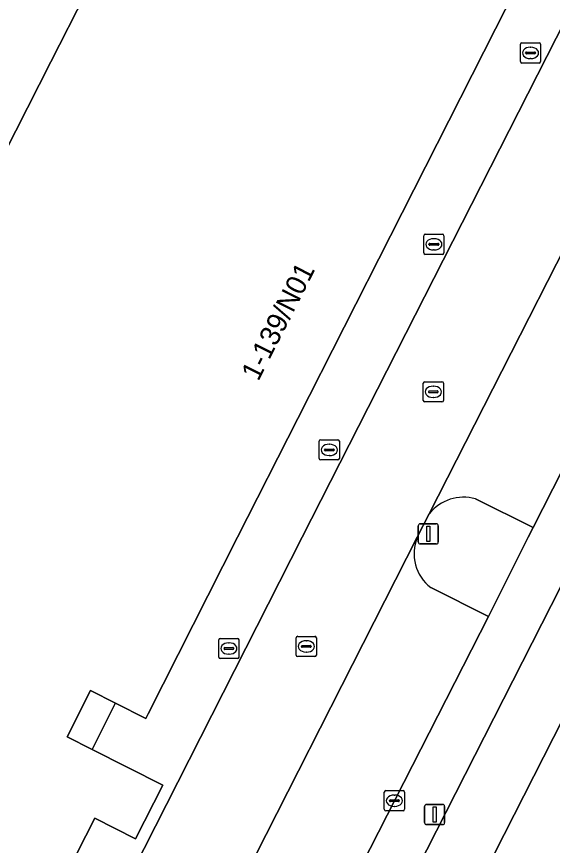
# Model space of a CAD drawing. Extents: x 161241 to 161758, y 384138 to 384885.
# Drawn here: x 161558.34 to 161584.85, y 384484.75 to 384525.77 of the extents above; entities that cross this region are included whole.
import ezdxf

# ---------------------------------------------------------------- set-up
doc = ezdxf.new("R2010")
doc.units = 0
for name, color, linetype in [('IMGEO_Berm_groen', 7, 'Continuous'), ('IMGEO_Erf', 7, 'Continuous'), ('IMGEO_Fietspad_gesloten', 7, 'Continuous'), ('IMGEO_Groenvoorziening', 7, 'Continuous'), ('IMGEO_Haag', 7, 'Continuous'), ('IMGEO_Kolk', 7, 'Continuous'), ('IMGEO_Lichtmast', 7, 'Continuous'), ('IMGEO_Pand', 7, 'Continuous'), ('IMGEO_Pand_nummerreeks', 7, 'Continuous'), ('IMGEO_Pand_overbouw', 7, 'Continuous'), ('IMGEO_Parkeervlak_open', 7, 'Continuous'), ('IMGEO_Rijbaan_lokaal_open', 7, 'Continuous'), ('IMGEO_Rioolput', 7, 'Continuous'), ('IMGEO_Voetpad_open', 7, 'Continuous')]:
    doc.layers.add(name, color=color, linetype=linetype)

msp = doc.modelspace()

# ---------------------------------------------------------------- linework, layer by layer
at = {"layer": 'IMGEO_Berm_groen'}
msp.add_lwpolyline([(161628.393, 384575.761), (161628.195, 384575.423), (161627.927, 384574.874), (161627.772, 384574.506), (161627.114, 384573.143), (161550.415, 384422.299), (161526.535, 384375.146), (161520.707, 384363.649)], dxfattribs=at)
at = {"layer": 'IMGEO_Erf'}
msp.add_lwpolyline([(161545.574, 384495.041), (161546.917, 384494.362), (161549.173, 384498.829), (161547.837, 384499.52), (161548.081, 384500), (161550.264, 384504.297), (161555.424, 384514.452), (161560.039, 384523.536), (161565.227, 384533.748), (161567.615, 384538.447), (161568.979, 384537.766), (161570.138, 384540.132), (161570.443, 384542.795), (161568.946, 384542.971), (161569.566, 384548.298), (161570.885, 384559.629), (161572.061, 384569.733), (161573.384, 384581.093), (161574.574, 384591.319), (161575.896, 384602.674)], dxfattribs=at)
at = {"layer": 'IMGEO_Fietspad_gesloten'}
for points in [[(161627.927, 384574.874), (161628.195, 384575.423), (161625.518, 384576.727), (161548.308, 384424.931), (161522.72, 384374.49), (161518.014, 384365.014)], [(161520.707, 384363.649), (161526.535, 384375.146), (161550.415, 384422.299), (161627.114, 384573.143), (161627.772, 384574.506), (161627.927, 384574.874)]]:
    msp.add_lwpolyline(points, dxfattribs=at)
at = {"layer": 'IMGEO_Groenvoorziening'}
for points in [[(161583.652, 384500), (161583.893, 384500.478), (161581.038, 384501.902)], [(161578.756, 384501.165), (161578.163, 384500)], [(161578.826, 384497.506), (161581.681, 384496.083), (161583.652, 384500)]]:
    msp.add_lwpolyline(points, dxfattribs=at)
for centre, radius, start, end in [((161580.452, 384499.816), 2.167, 74.3044, 141.4926), ((161580.118, 384499.185), 2.118, 157.362, 232.4122)]:
    msp.add_arc(centre, radius, start, end, dxfattribs=at)
at = {"layer": 'IMGEO_Haag'}
for points in [[(161578.826, 384497.506), (161581.681, 384496.083), (161583.652, 384500), (161583.893, 384500.478), (161581.038, 384501.902)], [(161578.756, 384501.165), (161578.163, 384500)]]:
    msp.add_lwpolyline(points, dxfattribs=at)
for centre, radius, start, end in [((161580.452, 384499.816), 2.167, 74.3044, 141.4926), ((161580.118, 384499.185), 2.118, 157.362, 232.4122)]:
    msp.add_arc(centre, radius, start, end, dxfattribs=at)
at = {"layer": 'IMGEO_Kolk'}
for p, q in [((161578.456, 384506.773), (161578.456, 384507.625)), ((161578.531, 384507.699), (161579.383, 384507.699)), ((161579.457, 384507.625), (161579.457, 384506.773)), ((161578.715, 384507.193), (161578.715, 384507.205)), ((161579.153, 384507.156), (161578.755, 384507.156)), ((161578.758, 384507.242), (161579.156, 384507.242)), ((161578.944, 384507.479), (161578.969, 384507.479)), ((161579.199, 384507.205), (161579.199, 384507.193)), ((161579.383, 384506.699), (161578.531, 384506.699)), ((161578.967, 384506.919), (161578.942, 384506.919)), ((161572.172, 384494.17), (161572.172, 384495.022)), ((161572.247, 384495.096), (161573.099, 384495.096)), ((161572.66, 384494.876), (161572.685, 384494.876)), ((161573.173, 384495.022), (161573.173, 384494.17)), ((161572.431, 384494.59), (161572.431, 384494.602)), ((161572.869, 384494.553), (161572.471, 384494.553)), ((161572.474, 384494.639), (161572.872, 384494.639)), ((161572.915, 384494.602), (161572.915, 384494.59)), ((161573.099, 384494.096), (161572.247, 384494.096)), ((161572.683, 384494.316), (161572.658, 384494.316)), ((161576.606, 384487.46), (161577.458, 384487.46)), ((161576.531, 384486.534), (161576.531, 384487.386)), ((161576.833, 384487.003), (161577.231, 384487.003)), ((161577.019, 384487.24), (161577.044, 384487.24)), ((161577.532, 384487.386), (161577.532, 384486.534)), ((161576.79, 384486.954), (161576.79, 384486.966)), ((161577.228, 384486.917), (161576.83, 384486.917)), ((161577.042, 384486.68), (161577.017, 384486.68)), ((161577.274, 384486.966), (161577.274, 384486.954)), ((161577.458, 384486.46), (161576.606, 384486.46))]:
    msp.add_line(p, q, dxfattribs=at)
for points in [[(161578.456, 384506.773), (161578.456, 384507.625)], [(161578.531, 384507.699), (161579.383, 384507.699)], [(161579.457, 384507.625), (161579.457, 384506.773)], [(161579.383, 384506.699), (161578.531, 384506.699)], [(161572.172, 384494.17), (161572.172, 384495.022)], [(161572.247, 384495.096), (161573.099, 384495.096)], [(161573.173, 384495.022), (161573.173, 384494.17)], [(161573.099, 384494.096), (161572.247, 384494.096)], [(161576.606, 384487.46), (161577.458, 384487.46)], [(161576.531, 384486.534), (161576.531, 384487.386)], [(161577.532, 384487.386), (161577.532, 384486.534)], [(161577.458, 384486.46), (161576.606, 384486.46)]]:
    msp.add_lwpolyline(points, dxfattribs=at)
for centre, radius, start, end in [((161578.533, 384507.623), 0.0765, 91.552, 178.448), ((161578.533, 384507.623), 0.0765, 91.552, 178.448), ((161579.381, 384507.623), 0.0765, 1.552, 88.448), ((161579.381, 384507.623), 0.0765, 1.552, 88.448), ((161578.755, 384507.202), 0.0403, 85.8775, 175.7526), ((161578.752, 384507.192), 0.0366, 178.938, 274.7102), ((161579.156, 384507.199), 0.043, 264.8664, 352.4533), ((161579.16, 384507.204), 0.0386, 1.7309, 96.639), ((161578.533, 384506.775), 0.0765, 181.552, 268.448), ((161578.533, 384506.775), 0.0765, 181.552, 268.448), ((161579.381, 384506.775), 0.0765, 271.552, 358.448), ((161579.381, 384506.775), 0.0765, 271.552, 358.448), ((161572.249, 384495.02), 0.0765, 91.552, 178.448), ((161572.249, 384495.02), 0.0765, 91.552, 178.448), ((161573.097, 384495.02), 0.0765, 1.552, 88.448), ((161573.097, 384495.02), 0.0765, 1.552, 88.448), ((161572.471, 384494.599), 0.0403, 85.8775, 175.7526), ((161572.468, 384494.589), 0.0366, 178.938, 274.7102), ((161572.872, 384494.596), 0.043, 264.8664, 352.4533), ((161572.876, 384494.601), 0.0386, 1.7309, 96.639), ((161572.249, 384494.172), 0.0765, 181.552, 268.448), ((161572.249, 384494.172), 0.0765, 181.552, 268.448), ((161573.097, 384494.172), 0.0765, 271.552, 358.448), ((161573.097, 384494.172), 0.0765, 271.552, 358.448), ((161576.608, 384487.384), 0.0765, 91.552, 178.448), ((161576.608, 384487.384), 0.0765, 91.552, 178.448), ((161577.456, 384487.384), 0.0765, 1.552, 88.448), ((161577.456, 384487.384), 0.0765, 1.552, 88.448), ((161576.83, 384486.963), 0.0403, 85.8775, 175.7526), ((161577.235, 384486.965), 0.0386, 1.7309, 96.639), ((161576.827, 384486.953), 0.0366, 178.938, 274.7102), ((161577.231, 384486.96), 0.043, 264.8664, 352.4533), ((161576.608, 384486.536), 0.0765, 181.552, 268.448), ((161576.608, 384486.536), 0.0765, 181.552, 268.448), ((161577.456, 384486.536), 0.0765, 271.552, 358.448), ((161577.456, 384486.536), 0.0765, 271.552, 358.448)]:
    msp.add_arc(centre, radius, start, end, dxfattribs=at)
for centre, major_axis, ratio, start_param, end_param in [((161578.943, 384507.199), (-0.387, 0.002), 0.722429, 4.712389, 7.853982), ((161578.968, 384507.199), (-0.39, 0.002), 0.717154, 1.570796, 4.712389), ((161572.659, 384494.596), (-0.387, 0.002), 0.722429, 4.712389, 7.853982), ((161572.684, 384494.596), (-0.39, 0.002), 0.717154, 1.570796, 4.712389), ((161577.018, 384486.96), (-0.387, 0.002), 0.722429, 4.712389, 7.853982), ((161577.043, 384486.96), (-0.39, 0.002), 0.717154, 1.570796, 4.712389)]:
    msp.add_ellipse(centre, major_axis=major_axis, ratio=ratio, start_param=start_param, end_param=end_param, dxfattribs=at)
at = {"layer": 'IMGEO_Lichtmast'}
for p, q in [((161578.211, 384499.768), (161578.211, 384500.568)), ((161578.211, 384500.568), (161578.211, 384499.768)), ((161578.311, 384500.668), (161579.101, 384500.668)), ((161579.101, 384500.668), (161578.311, 384500.668)), ((161579.201, 384500.568), (161579.201, 384499.768)), ((161579.201, 384499.768), (161579.201, 384500.568)), ((161579.101, 384499.668), (161578.311, 384499.668)), ((161578.311, 384499.668), (161579.101, 384499.668)), ((161578.523, 384485.876), (161578.523, 384486.676)), ((161578.523, 384486.676), (161578.523, 384485.876)), ((161578.623, 384486.776), (161579.413, 384486.776)), ((161579.413, 384486.776), (161578.623, 384486.776)), ((161579.513, 384486.676), (161579.513, 384485.876)), ((161579.513, 384485.876), (161579.513, 384486.676)), ((161579.413, 384485.776), (161578.623, 384485.776)), ((161578.623, 384485.776), (161579.413, 384485.776))]:
    msp.add_line(p, q, dxfattribs=at)
for points in [[(161578.631, 384500.543), (161578.781, 384500.543), (161578.781, 384499.793), (161578.631, 384499.793), (161578.631, 384500.543)], [(161578.943, 384486.651), (161579.093, 384486.651), (161579.093, 384485.901), (161578.943, 384485.901), (161578.943, 384486.651)]]:
    msp.add_lwpolyline(points, dxfattribs=at)
for centre, start, end in [((161578.311, 384500.568), 90, 180), ((161578.311, 384500.568), 90, 180), ((161579.101, 384500.568), 0, 90), ((161579.101, 384500.568), 360, 90), ((161578.311, 384499.768), 180, 270), ((161578.311, 384499.768), 180, 270), ((161579.101, 384499.768), 270, 0), ((161579.101, 384499.768), 270, 0), ((161578.623, 384486.676), 90, 180), ((161578.623, 384486.676), 90, 180), ((161579.413, 384486.676), 0, 90), ((161579.413, 384486.676), 360, 90), ((161578.623, 384485.876), 180, 270), ((161578.623, 384485.876), 180, 270), ((161579.413, 384485.876), 270, 0), ((161579.413, 384485.876), 270, 0)]:
    msp.add_arc(centre, 0.1, start, end, dxfattribs=at)
at = {"layer": 'IMGEO_Pand'}
for points in [[(161565.227, 384533.748), (161560.039, 384523.536), (161555.424, 384514.452), (161550.264, 384504.297), (161548.081, 384500), (161547.837, 384499.52), (161549.173, 384498.829), (161546.917, 384494.362), (161545.574, 384495.041), (161543.125, 384490.234), (161537.947, 384480.074), (161533.323, 384471), (161528.137, 384460.824)], [(161545.025, 384452.253), (161550.195, 384462.432), (161554.798, 384471.495), (161559.976, 384481.689), (161562.212, 384486.092), (161564.22, 384485.074), (161565.568, 384487.732), (161562.083, 384489.499), (161560.841, 384490.129), (161561.999, 384492.413), (161563.241, 384491.783), (161564.728, 384491.029), (161564.842, 384491.252), (161567.082, 384495.672), (161569.275, 384500), (161572.257, 384505.884), (161576.837, 384514.921), (161582.032, 384525.172), (161584.435, 384529.913)]]:
    msp.add_lwpolyline(points, dxfattribs=at)
at = {"layer": 'IMGEO_Pand_overbouw'}
msp.add_lwpolyline([(161563.241, 384491.783), (161561.999, 384492.413), (161560.841, 384490.129), (161562.083, 384489.499)], close=True, dxfattribs=at)
at = {"layer": 'IMGEO_Parkeervlak_open'}
for points in [[(161589.551, 384522.382), (161578.756, 384501.165)], [(161581.038, 384501.902), (161583.893, 384500.478), (161593.085, 384518.552), (161590.622, 384519.822)], [(161578.163, 384500), (161567.484, 384478.988), (161567.177, 384478.384)], [(161569.793, 384479.275), (161572.488, 384478.024), (161581.681, 384496.083), (161578.826, 384497.506)]]:
    msp.add_lwpolyline(points, dxfattribs=at)
for centre, radius, start, end in [((161580.452, 384499.816), 2.167, 74.3044, 141.4926), ((161580.118, 384499.185), 2.118, 157.362, 232.4122)]:
    msp.add_arc(centre, radius, start, end, dxfattribs=at)
at = {"layer": 'IMGEO_Rijbaan_lokaal_open'}
msp.add_lwpolyline([(161567.484, 384478.988), (161578.163, 384500), (161578.756, 384501.165), (161589.551, 384522.382), (161590.063, 384523.389), (161593.299, 384529.749), (161594.18, 384531.478), (161588.813, 384532.151), (161588.763, 384532.053), (161572.473, 384500), (161562.971, 384481.279)], close=True, dxfattribs=at)
at = {"layer": 'IMGEO_Rioolput'}
for p, q in [((161583.263, 384523.549), (161583.263, 384524.401)), ((161583.338, 384524.475), (161584.19, 384524.475)), ((161584.264, 384524.401), (161584.264, 384523.549)), ((161583.522, 384523.969), (161583.522, 384523.981)), ((161583.96, 384523.932), (161583.562, 384523.932)), ((161583.565, 384524.018), (161583.963, 384524.018)), ((161583.751, 384524.255), (161583.776, 384524.255)), ((161584.006, 384523.981), (161584.006, 384523.969)), ((161583.774, 384523.695), (161583.749, 384523.695)), ((161584.19, 384523.475), (161583.338, 384523.475)), ((161578.482, 384514.074), (161578.482, 384514.926)), ((161578.557, 384515), (161579.409, 384515)), ((161579.483, 384514.926), (161579.483, 384514.074)), ((161578.741, 384514.494), (161578.741, 384514.506)), ((161578.784, 384514.543), (161579.182, 384514.543)), ((161578.97, 384514.78), (161578.995, 384514.78)), ((161579.225, 384514.506), (161579.225, 384514.494)), ((161579.179, 384514.457), (161578.781, 384514.457)), ((161578.993, 384514.22), (161578.968, 384514.22)), ((161579.409, 384514), (161578.557, 384514)), ((161573.31, 384503.899), (161573.31, 384504.751)), ((161573.385, 384504.825), (161574.237, 384504.825)), ((161574.311, 384504.751), (161574.311, 384503.899)), ((161573.569, 384504.319), (161573.569, 384504.331)), ((161574.007, 384504.282), (161573.609, 384504.282)), ((161573.612, 384504.368), (161574.01, 384504.368)), ((161573.798, 384504.605), (161573.823, 384504.605)), ((161574.053, 384504.331), (161574.053, 384504.319)), ((161574.237, 384503.825), (161573.385, 384503.825)), ((161573.821, 384504.045), (161573.796, 384504.045)), ((161568.342, 384494.068), (161568.342, 384494.92)), ((161568.417, 384494.994), (161569.269, 384494.994)), ((161569.343, 384494.92), (161569.343, 384494.068)), ((161568.601, 384494.488), (161568.601, 384494.5)), ((161569.039, 384494.451), (161568.641, 384494.451)), ((161568.644, 384494.537), (161569.042, 384494.537)), ((161568.83, 384494.774), (161568.855, 384494.774)), ((161569.085, 384494.5), (161569.085, 384494.488)), ((161569.269, 384493.994), (161568.417, 384493.994)), ((161568.853, 384494.214), (161568.828, 384494.214))]:
    msp.add_line(p, q, dxfattribs=at)
for points in [[(161583.263, 384523.549), (161583.263, 384524.401)], [(161583.338, 384524.475), (161584.19, 384524.475)], [(161584.264, 384524.401), (161584.264, 384523.549)], [(161584.19, 384523.475), (161583.338, 384523.475)], [(161578.482, 384514.074), (161578.482, 384514.926)], [(161578.557, 384515), (161579.409, 384515)], [(161579.483, 384514.926), (161579.483, 384514.074)], [(161579.409, 384514), (161578.557, 384514)], [(161573.31, 384503.899), (161573.31, 384504.751)], [(161573.385, 384504.825), (161574.237, 384504.825)], [(161574.311, 384504.751), (161574.311, 384503.899)], [(161574.237, 384503.825), (161573.385, 384503.825)], [(161568.342, 384494.068), (161568.342, 384494.92)], [(161568.417, 384494.994), (161569.269, 384494.994)], [(161569.343, 384494.92), (161569.343, 384494.068)], [(161569.269, 384493.994), (161568.417, 384493.994)]]:
    msp.add_lwpolyline(points, dxfattribs=at)
for centre, radius, start, end in [((161583.34, 384524.399), 0.0765, 91.552, 178.448), ((161583.34, 384524.399), 0.0765, 91.552, 178.448), ((161584.188, 384524.399), 0.0765, 1.552, 88.448), ((161584.188, 384524.399), 0.0765, 1.552, 88.448), ((161583.562, 384523.978), 0.0403, 85.8775, 175.7526), ((161583.559, 384523.968), 0.0366, 178.938, 274.7102), ((161583.963, 384523.975), 0.043, 264.8664, 352.4533), ((161583.967, 384523.98), 0.0386, 1.7309, 96.639), ((161583.34, 384523.551), 0.0765, 181.552, 268.448), ((161583.34, 384523.551), 0.0765, 181.552, 268.448), ((161584.188, 384523.551), 0.0765, 271.552, 358.448), ((161584.188, 384523.551), 0.0765, 271.552, 358.448), ((161578.559, 384514.924), 0.0765, 91.552, 178.448), ((161578.559, 384514.924), 0.0765, 91.552, 178.448), ((161579.407, 384514.924), 0.0765, 1.552, 88.448), ((161579.407, 384514.924), 0.0765, 1.552, 88.448), ((161578.781, 384514.503), 0.0403, 85.8775, 175.7526), ((161578.778, 384514.493), 0.0366, 178.938, 274.7102), ((161579.182, 384514.5), 0.043, 264.8664, 352.4533), ((161579.186, 384514.505), 0.0386, 1.7309, 96.639), ((161578.559, 384514.076), 0.0765, 181.552, 268.448), ((161578.559, 384514.076), 0.0765, 181.552, 268.448), ((161579.407, 384514.076), 0.0765, 271.552, 358.448), ((161579.407, 384514.076), 0.0765, 271.552, 358.448), ((161573.387, 384504.749), 0.0765, 91.552, 178.448), ((161573.387, 384504.749), 0.0765, 91.552, 178.448), ((161574.235, 384504.749), 0.0765, 1.552, 88.448), ((161574.235, 384504.749), 0.0765, 1.552, 88.448), ((161573.609, 384504.328), 0.0403, 85.8775, 175.7526), ((161573.606, 384504.318), 0.0366, 178.938, 274.7102), ((161574.01, 384504.325), 0.043, 264.8664, 352.4533), ((161574.014, 384504.33), 0.0386, 1.7309, 96.639), ((161573.387, 384503.901), 0.0765, 181.552, 268.448), ((161573.387, 384503.901), 0.0765, 181.552, 268.448), ((161574.235, 384503.901), 0.0765, 271.552, 358.448), ((161574.235, 384503.901), 0.0765, 271.552, 358.448), ((161568.419, 384494.918), 0.0765, 91.552, 178.448), ((161568.419, 384494.918), 0.0765, 91.552, 178.448), ((161569.267, 384494.918), 0.0765, 1.552, 88.448), ((161569.267, 384494.918), 0.0765, 1.552, 88.448), ((161568.641, 384494.497), 0.0403, 85.8775, 175.7526), ((161568.638, 384494.487), 0.0366, 178.938, 274.7102), ((161569.042, 384494.494), 0.043, 264.8664, 352.4533), ((161569.046, 384494.499), 0.0386, 1.7309, 96.639), ((161568.419, 384494.07), 0.0765, 181.552, 268.448), ((161568.419, 384494.07), 0.0765, 181.552, 268.448), ((161569.267, 384494.07), 0.0765, 271.552, 358.448), ((161569.267, 384494.07), 0.0765, 271.552, 358.448)]:
    msp.add_arc(centre, radius, start, end, dxfattribs=at)
for centre, major_axis, ratio, start_param, end_param in [((161583.75, 384523.975), (-0.387, 0.002), 0.722429, 4.712389, 7.853982), ((161583.775, 384523.975), (-0.39, 0.002), 0.717154, 1.570796, 4.712389), ((161578.969, 384514.5), (-0.387, 0.002), 0.722429, 4.712389, 7.853982), ((161578.994, 384514.5), (-0.39, 0.002), 0.717154, 1.570796, 4.712389), ((161573.797, 384504.325), (-0.387, 0.002), 0.722429, 4.712389, 7.853982), ((161573.822, 384504.325), (-0.39, 0.002), 0.717154, 1.570796, 4.712389), ((161568.829, 384494.494), (-0.387, 0.002), 0.722429, 4.712389, 7.853982), ((161568.854, 384494.494), (-0.39, 0.002), 0.717154, 1.570796, 4.712389)]:
    msp.add_ellipse(centre, major_axis=major_axis, ratio=ratio, start_param=start_param, end_param=end_param, dxfattribs=at)
at = {"layer": 'IMGEO_Voetpad_open'}
for points in [[(161561.636, 384478.649), (161562.971, 384481.279), (161572.473, 384500), (161588.763, 384532.053), (161588.813, 384532.151), (161589.606, 384533.711), (161590.1, 384534.683), (161590.199, 384534.878), (161596.833, 384592.139), (161597.172, 384595.069), (161599.25, 384613.004)], [(161633.327, 384597.149), (161633.111, 384597.461), (161632.647, 384596.649), (161631.2, 384593.755), (161623.4, 384578.41), (161612.501, 384556.942), (161601.206, 384534.744), (161601.061, 384534.46), (161600.997, 384534.334), (161598.988, 384530.383), (161598.728, 384529.872), (161598.639, 384529.691), (161595.33, 384522.974), (161593.085, 384518.552), (161583.893, 384500.478), (161583.652, 384500), (161581.681, 384496.083), (161572.488, 384478.024), (161570.493, 384474.049), (161561.138, 384455.713), (161559.035, 384451.577)], [(161518.014, 384365.014), (161522.72, 384374.49), (161548.308, 384424.931), (161625.518, 384576.727)], [(161584.435, 384529.913), (161582.032, 384525.172), (161576.837, 384514.921), (161572.257, 384505.884), (161569.275, 384500), (161567.082, 384495.672), (161564.842, 384491.252), (161564.728, 384491.029), (161563.241, 384491.783), (161561.999, 384492.413), (161560.841, 384490.129), (161562.083, 384489.499), (161565.568, 384487.732), (161564.22, 384485.074), (161562.212, 384486.092), (161559.976, 384481.689), (161554.798, 384471.495), (161550.195, 384462.432), (161545.025, 384452.253)]]:
    msp.add_lwpolyline(points, dxfattribs=at)

# ---------------------------------------------------------------- texts
at = {"layer": 'IMGEO_Pand_nummerreeks'}
msp.add_text('1-139/N01', height=1, rotation=63.1113, dxfattribs=at).set_placement((161570.299, 384507.685))

doc.saveas('drawing.dxf')
